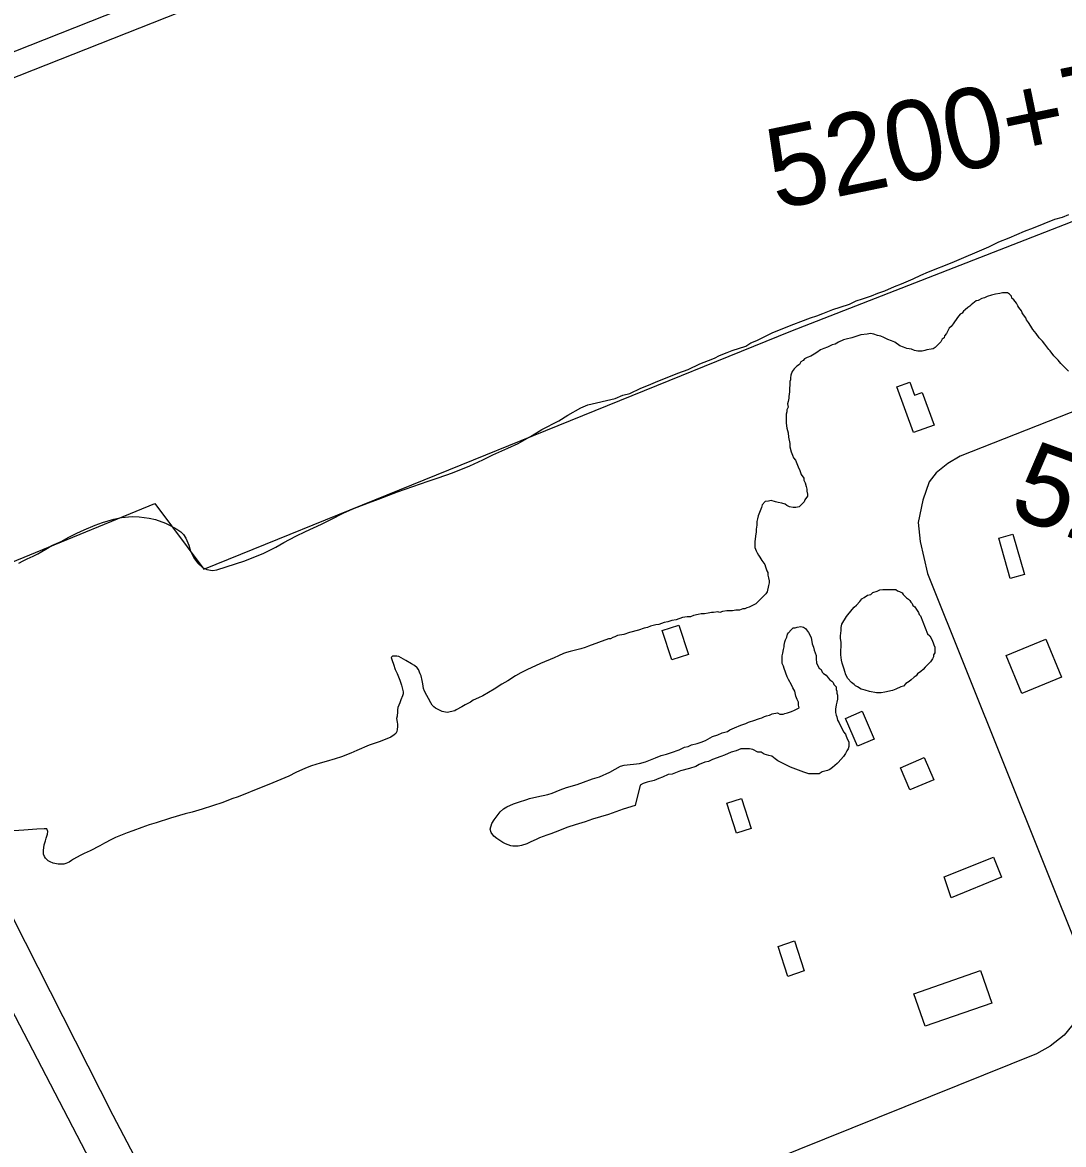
# Model space of a CAD drawing. Extents: x 3324125 to 3362000, y 600753 to 626151.
# Drawn here: x 3330131 to 3331428, y 615545 to 616943 of the extents above; entities that cross this region are included whole.
import ezdxf

# ---------------------------------------------------------------- set-up
doc = ezdxf.new("R2010")
doc.units = 0
for name, color, linetype in [('V-BLDG-OTLN', 7, 'Continuous'), ('V-ROAD-CNTR', 7, 'Continuous'), ('V-SITE-VEGE', 7, 'Continuous'), ('V-SURV-IDEN', 7, 'Continuous'), ('V-TOPO-SHOR', 7, 'Continuous')]:
    doc.layers.add(name, color=color, linetype=linetype)

msp = doc.modelspace()

# ---------------------------------------------------------------- linework, layer by layer
at = {"layer": 'V-BLDG-OTLN'}
for points in [[(3331251.8, 616482.1), (3331266.7, 616441.5), (3331240.9, 616432), (3331220, 616488.9), (3331236.3, 616494.9), (3331242.3, 616478.6)], [(3331364.8, 616305.5), (3331379.2, 616255.3), (3331361.6, 616250.2), (3331347.2, 616300.5)], [(3330948.7, 616192.1), (3330960.5, 616155.6), (3330939.7, 616149), (3330927.9, 616185.4)], [(3331356.5, 616154.2), (3331405.9, 616174.5), (3331425.4, 616127.2), (3331376, 616106.8)], [(3331177, 616084.9), (3331192, 616050.3), (3331171.3, 616041.3), (3331156.3, 616076)], [(3331254.4, 616027.3), (3331266.2, 615999.6), (3331236.4, 615986.9), (3331224.6, 616014.6)], [(3331026.5, 615976.3), (3331038.6, 615938.9), (3331020.4, 615933), (3331008.2, 615970.3)], [(3331279.2, 615878.5), (3331340.6, 615902.9), (3331350.7, 615878), (3331287.8, 615852.6)], [(3331092.8, 615798.7), (3331104.9, 615761.3), (3331084.5, 615754.6), (3331072.3, 615792)], [(3331241.5, 615732.8), (3331324.5, 615761.7), (3331338.6, 615721.3), (3331255.6, 615692.4)]]:
    msp.add_lwpolyline(points, close=True, dxfattribs=at)
at = {"layer": 'V-ROAD-CNTR'}
for points in [[(3328654.4, 618531.3), (3329365.9, 617157.1), (3329945, 616043.4), (3330528.3, 614922), (3330989.5, 614026.8), (3331101.4, 613813.5), (3331202.1, 613623.7), (3331288.2, 613468), (3331370, 613325.9), (3331489, 613122.4), (3331566.5, 612992.9), (3331683.8, 612804.9), (3331896.1, 612486.7), (3332030.8, 612296.1), (3332261.4, 611985.3), (3332414.1, 611792.3), (3332593.4, 611567.9), (3332751.8, 611383.2), (3332947.9, 611162.2), (3333176.2, 610911.4), (3333408.7, 610672.1), (3333754.4, 610344.1), (3333997.3, 610124.4), (3334416.3, 609777.9)], [(3329622.7, 616703.3), (3329633, 616708.7), (3329640.7, 616710), (3329667.1, 616715.1), (3329709.7, 616718.1), (3329737.4, 616721.6), (3329760, 616732.4), (3330393.7, 616983), (3332211.8, 617656.7), (3332230.2, 617667.1), (3332245.9, 617675.2), (3332252, 617676.6), (3332287.8, 617678.2)], [(3329608.8, 616729.9), (3329623.3, 616737.5), (3329635.4, 616739.5), (3329663.2, 616744.9), (3329706.7, 616747.9), (3329728.8, 616750.8), (3329748, 616759.9), (3330382.9, 617011), (3330469.2, 617043)], [(3332062.8, 616703.3), (3331299.1, 616402.5), (3331283.7, 616393.5), (3331269.2, 616382.1), (3331260.5, 616370.6), (3331252.7, 616347.9), (3331246.8, 616320), (3331249.3, 616296.2), (3331258.3, 616256.3), (3331450.3, 615777.5), (3331453.2, 615748.7), (3331451.9, 615720), (3331443.3, 615699.2), (3331428.9, 615681.4), (3331411.3, 615667.7), (3331394.3, 615658.1), (3330239.3, 615193.5), (3328629.8, 614542.4), (3328220.6, 614377)]]:
    msp.add_lwpolyline(points, dxfattribs=at)
at = {"layer": 'V-SITE-VEGE'}
for points in [[(3330960.1, 616510.7), (3330974.5, 616517.8), (3330985.7, 616521.7), (3330992.9, 616524.8), (3330999.3, 616528), (3331008.8, 616531.9), (3331015.2, 616534.2), (3331032, 616539.7), (3331038.4, 616543.7), (3331045.6, 616546.8), (3331064.8, 616556.2), (3331075.9, 616560.9), (3331091.9, 616567.2), (3331100.7, 616570.3), (3331112.7, 616575), (3331120.6, 616577.4), (3331127.8, 616580.5), (3331140.6, 616585.2), (3331149.4, 616588.3), (3331161.4, 616592.2), (3331169.4, 616596.2), (3331177.3, 616598.5), (3331188.5, 616602.4), (3331196.5, 616605.6), (3331205.3, 616608.7), (3331217.3, 616614.2), (3331226, 616617.3), (3331240.4, 616623.6), (3331250, 616628.3), (3331259.6, 616632.2), (3331289.1, 616644), (3331334.7, 616663.6), (3331347.5, 616669.9), (3331360.2, 616674.6), (3331379.4, 616683.2), (3331390.6, 616687.1), (3331416.9, 616698.1), (3331426.5, 616700.5), (3331434.5, 616703.6)], [(3331434, 616508.4), (3331424.5, 616518.1), (3331421.4, 616522.1), (3331415.8, 616527.7), (3331411.1, 616534.1), (3331409.5, 616535.7), (3331404.8, 616542.1), (3331401.6, 616546.1), (3331397.7, 616550.1), (3331393.7, 616555.7), (3331389.8, 616560.5), (3331387.4, 616564.5), (3331384.2, 616569.3), (3331381.9, 616572.5), (3331381.1, 616574.9), (3331377.9, 616578.9), (3331376.4, 616581.3), (3331375.6, 616583.7), (3331372.4, 616587.7), (3331370.8, 616590.1), (3331369.3, 616593.3), (3331366.1, 616597.3), (3331363.7, 616599.7), (3331363, 616602.1), (3331360.6, 616604.5), (3331358.2, 616606.1), (3331351.8, 616606.2), (3331348.6, 616605.4), (3331343.1, 616604.6), (3331338.3, 616603.1), (3331332.7, 616601.5), (3331329.5, 616599.9), (3331326.3, 616599.2), (3331321.5, 616596.8), (3331319.1, 616596), (3331312.7, 616591.3), (3331311.1, 616589.7), (3331308.7, 616588.1), (3331305.5, 616584.9), (3331303.1, 616583.4), (3331301.5, 616581), (3331299.1, 616579.4), (3331295.9, 616575.4), (3331294.3, 616573.1), (3331291.9, 616569.9), (3331290.2, 616567.5), (3331287.8, 616564.3), (3331285.4, 616562), (3331282.2, 616555.6), (3331279.8, 616552.5), (3331279, 616550.1), (3331276.6, 616548.5), (3331275, 616545.3), (3331267.8, 616538.2), (3331265.4, 616536.6), (3331263, 616535.8), (3331257.4, 616535.1), (3331255, 616534.3), (3331251.8, 616533.5), (3331246.2, 616533.6), (3331242.2, 616534.4), (3331238.3, 616536), (3331232.7, 616536.8)], [(3331232.7, 616536.8), (3331228.7, 616538.4), (3331224, 616540.1), (3331217.6, 616544.9), (3331213.6, 616546.5), (3331208.9, 616548.1), (3331204.1, 616550.6), (3331200.1, 616552.2), (3331196.2, 616553), (3331191.4, 616554.6), (3331187.4, 616555.4), (3331183.4, 616554.7), (3331175.5, 616553.9), (3331169.1, 616551.6), (3331164.3, 616550), (3331157.1, 616548.5), (3331153.9, 616547.7), (3331147.5, 616544.5), (3331143.5, 616542.2), (3331139.5, 616541.4), (3331133.9, 616538.3), (3331129.1, 616536.7), (3331125.2, 616535.1), (3331120.4, 616532), (3331117.2, 616529.6), (3331113.2, 616527.2), (3331108.4, 616525.7), (3331105.2, 616524.1), (3331103.6, 616521.7), (3331100.4, 616520.2), (3331098.8, 616517), (3331095.6, 616514.6), (3331092.3, 616511.4), (3331089.9, 616508.3), (3331088.3, 616503.5), (3331087.5, 616500.3), (3331087.5, 616497.9), (3331086.7, 616495.6), (3331086.6, 616482.8), (3331085.8, 616477.2), (3331085.7, 616474.8), (3331084.9, 616470.9), (3331084.1, 616467.7), (3331084.9, 616463.7), (3331083.3, 616460.5), (3331083.2, 616458.1), (3331082.4, 616455), (3331082.4, 616443.8), (3331083.1, 616437.4), (3331084.7, 616431.8), (3331085.4, 616426.3), (3331087, 616418.3), (3331086.9, 616414.3), (3331088.5, 616407.9), (3331090.1, 616403.9), (3331091.6, 616400.7), (3331094, 616397.5), (3331097.1, 616389.5), (3331099.5, 616384.8), (3331101.1, 616380), (3331104.2, 616375.2), (3331104.2, 616372.8), (3331105.8, 616369.6), (3331107.3, 616364.8), (3331108.1, 616361.6), (3331108.1, 616359.2), (3331108.9, 616355.2), (3331108.8, 616352.8), (3331105.6, 616348.1), (3331104.8, 616345.7), (3331098.4, 616339.4), (3331094.4, 616338.6), (3331091.2, 616338.6), (3331086.5, 616339.4), (3331083.3, 616341.1), (3331080.9, 616342.7), (3331076.9, 616344.3), (3331072.2, 616345.1), (3331069, 616345.9), (3331063.4, 616347.6), (3331060.2, 616346.8), (3331056.2, 616346), (3331052.2, 616342), (3331051.4, 616338.9), (3331047.4, 616328.5), (3331046.5, 616324.6), (3331045.7, 616321.4), (3331045.7, 616316.6), (3331044.9, 616311.8), (3331044.8, 616308.6), (3331044, 616303.1), (3331043.2, 616295.9), (3331043.1, 616288.7), (3331044.7, 616284.7), (3331046.3, 616282.3), (3331047.8, 616279.2), (3331049.4, 616276.7), (3331051.8, 616272.8), (3331055.7, 616267.9), (3331056.5, 616264.8), (3331058.1, 616260)], [(3330126.2, 616269.4), (3330131.4, 616272.2), (3330136.3, 616274.7), (3330143.9, 616278.2), (3330149.6, 616281.2), (3330159.5, 616287), (3330167.3, 616291.2), (3330178.6, 616296.4), (3330188.5, 616301.6), (3330198.5, 616306.6), (3330207.4, 616310.8), (3330221.3, 616316.7), (3330230.4, 616320), (3330244.4, 616324.3), (3330253.8, 616326.2), (3330267.4, 616327.5), (3330275.9, 616327), (3330288.3, 616325.6), (3330296.5, 616323.6), (3330308.7, 616319.4), (3330314.7, 616316.1), (3330322.8, 616311.8), (3330327.8, 616308.6), (3330331.1, 616305.1), (3330334, 616300.6), (3330337.8, 616291.9), (3330339.9, 616284.5), (3330344.9, 616274.7), (3330348.9, 616269.3), (3330355.1, 616263.8), (3330360.2, 616261.4), (3330367.3, 616260.4), (3330372.8, 616261.2), (3330407.8, 616272.4), (3330431.2, 616281.9), (3330446.4, 616289.4), (3330456.1, 616295), (3330471.1, 616302.9), (3330483.4, 616308.8), (3330503.1, 616318), (3330515, 616323.9), (3330530.4, 616331.8), (3330542.4, 616337), (3330561.7, 616344.4), (3330574.4, 616349), (3330598.1, 616358.4), (3330636.1, 616371.5), (3330648.7, 616375.5), (3330666.6, 616381.8), (3330688.1, 616390.6), (3330704.4, 616398.3), (3330716.7, 616404.2), (3330735.4, 616412.6), (3330748.3, 616418.6), (3330765.6, 616428.4), (3330777.9, 616435.7), (3330798.9, 616446.8), (3330810.4, 616453.9), (3330826.4, 616463.1), (3330835, 616466.6), (3330869.1, 616474.7), (3330878.7, 616478.6), (3330887.4, 616480.9), (3330901, 616487.2), (3330910.6, 616491.1), (3330919.4, 616495), (3330947.3, 616506), (3330960.1, 616510.7)], [(3331058.1, 616260), (3331059.6, 616257.6), (3331059.6, 616254.4), (3331060.4, 616251.2), (3331061.2, 616247.2), (3331061.2, 616244.8), (3331060.3, 616241.6), (3331058.7, 616233.7), (3331057.1, 616231.3), (3331044.3, 616218.6), (3331036.3, 616214.7), (3331033.1, 616213.9), (3331030.7, 616212.4), (3331028.3, 616212.4), (3331024.3, 616210.8), (3331019.5, 616210.8), (3331015.5, 616210.1), (3331008.4, 616210.1), (3331002.8, 616209.3), (3330999.6, 616207.8), (3330997.2, 616208.6), (3330991.6, 616207.8), (3330989.2, 616207.8), (3330985.2, 616207.1), (3330980.5, 616206.3), (3330976.5, 616206.3), (3330972.5, 616205.6), (3330966.9, 616204), (3330962.9, 616202.4), (3330958.9, 616202.5), (3330953.3, 616201.7), (3330945.4, 616198.6), (3330939.8, 616197.8), (3330935, 616196.2), (3330930.2, 616195.5), (3330923.8, 616193.1), (3330919.8, 616192.4), (3330913.4, 616190.8), (3330909.5, 616189.2), (3330905.5, 616188.5), (3330898.3, 616186.1), (3330887.1, 616183), (3330879.9, 616180.7), (3330872, 616179.1), (3330868.8, 616177.6), (3330866.4, 616176.8), (3330863.2, 616175.2), (3330860.8, 616175.2), (3330836, 616165.9), (3330834, 616165.3), (3330831.7, 616164.2), (3330826.4, 616162.5), (3330816.5, 616160), (3330813.2, 616159.5), (3330808.5, 616158.1), (3330804.6, 616156.8), (3330798.6, 616154.1), (3330793.3, 616151.6), (3330776, 616144.5), (3330758.9, 616136.5), (3330751.7, 616132.9), (3330745, 616129.2), (3330735.3, 616122.9), (3330728.1, 616118.8), (3330718.3, 616112.3), (3330704.1, 616104), (3330699, 616101.7), (3330692.4, 616098.5), (3330688.7, 616096.2), (3330682.4, 616092.7), (3330678.2, 616090.2), (3330671.1, 616086.6), (3330669.4, 616085.4), (3330659.9, 616083.3), (3330653.6, 616084.7), (3330650.2, 616086.3), (3330645.1, 616088.9), (3330643.2, 616090.4), (3330641.3, 616092.4), (3330639.3, 616095.5), (3330636.7, 616100.8), (3330634.4, 616104.5), (3330631.5, 616109.7), (3330630.5, 616113.1), (3330629.4, 616118.9), (3330628.8, 616123), (3330627.5, 616129), (3330626.2, 616131.7), (3330624.1, 616136.8), (3330622.3, 616138.9), (3330619.1, 616141.7), (3330615.4, 616144), (3330608.2, 616148.2), (3330599.5, 616152.9), (3330597, 616153.5), (3330591.9, 616153.7), (3330590, 616151.8), (3330591.1, 616148.1), (3330593, 616143.6), (3330595.1, 616137), (3330597.4, 616131.9)], [(3330919.6, 616026.7), (3330926.7, 616029.8), (3330933.1, 616031.4), (3330939.5, 616033.7), (3330949.1, 616036.8), (3330955.5, 616040), (3330960.3, 616040.8), (3330964.3, 616043.1), (3330971.4, 616044.7), (3330976.2, 616046.2), (3330981.8, 616048.6), (3330990.6, 616053.3), (3330997, 616055.7), (3331002.6, 616058), (3331009, 616059.6), (3331012.2, 616061.9), (3331017.8, 616064.3), (3331025.8, 616067.4), (3331032.1, 616069.8), (3331035.3, 616071.3), (3331037.7, 616072.1), (3331040.9, 616072.9), (3331048.9, 616076), (3331052.1, 616076.8), (3331055.3, 616078.4), (3331057.7, 616079.2), (3331061.7, 616079.9), (3331064.9, 616081.5), (3331071.3, 616083.1), (3331074.4, 616081.4), (3331078.4, 616081.4), (3331080.8, 616082.2), (3331084, 616083), (3331088.8, 616084.5), (3331092.8, 616086.1), (3331096, 616087.7), (3331098.4, 616089.2), (3331097.6, 616092.4), (3331097.6, 616096.4), (3331096.1, 616099.6), (3331094.5, 616103.6), (3331092.9, 616110), (3331090.6, 616114), (3331089, 616118), (3331085.1, 616124.4), (3331083.5, 616127.6), (3331079.6, 616138), (3331078.8, 616141.2), (3331077.2, 616144.3), (3331077.3, 616153.9), (3331078.1, 616157.1), (3331078.9, 616161.9), (3331079.8, 616165), (3331079.8, 616167.4), (3331080.6, 616171.4), (3331081.4, 616173.8), (3331083, 616177), (3331083.8, 616180.9), (3331085.4, 616182.5), (3331088.7, 616186.5), (3331091.1, 616188.9), (3331093.4, 616188.8), (3331095.8, 616189.6), (3331100.6, 616190.4), (3331103.8, 616189.6), (3331106.2, 616188), (3331107.8, 616186.4), (3331110.1, 616183.2), (3331113.3, 616176.8), (3331114.8, 616168.8), (3331116.4, 616164.8), (3331117.2, 616160.8), (3331119.5, 616154.4), (3331119.5, 616150.4), (3331120.2, 616144.9), (3331123.4, 616138.5), (3331125.8, 616136.9), (3331127.3, 616133.7), (3331128.9, 616132.1), (3331132.1, 616129.7), (3331134.5, 616126.5), (3331136.8, 616124), (3331139.2, 616122.4), (3331140.8, 616120.8), (3331141.6, 616118.4), (3331144.7, 616115.2), (3331144.7, 616112), (3331145.5, 616109.7), (3331145.5, 616107.3), (3331146.3, 616104.9), (3331146.2, 616100.1), (3331145.4, 616096.1), (3331144.6, 616092.9), (3331143.8, 616087.4), (3331143.7, 616083.4), (3331144.5, 616080.2), (3331145.3, 616077.8), (3331146.1, 616073.8)], [(3330597.4, 616131.9), (3330600.9, 616123.7), (3330602.8, 616117.5), (3330604.9, 616109.1), (3330605.2, 616106.4), (3330604.1, 616104.3), (3330602.1, 616099.3), (3330600.7, 616095.2), (3330598.5, 616089.4), (3330597.9, 616086.7), (3330597.9, 616084.1), (3330597.5, 616078.7), (3330596.7, 616075.8), (3330597.4, 616071.3), (3330598, 616068.6), (3330598, 616065.9), (3330597.4, 616062), (3330597.2, 616059.5), (3330595.8, 616057), (3330593.8, 616055.4), (3330589.7, 616052.7), (3330576.3, 616047.2), (3330562.7, 616042.6), (3330547.1, 616035.9), (3330539.9, 616032.6), (3330528, 616028.3), (3330520.2, 616025.6), (3330508.9, 616022.2), (3330501.5, 616020.3), (3330490.7, 616016.8), (3330483.2, 616013.8), (3330471.4, 616008.4), (3330462.4, 616004), (3330437.5, 615993.7), (3330428.1, 615989.7), (3330399.5, 615978.4), (3330391.5, 615975.7), (3330380.4, 615971.3), (3330354.3, 615962.8), (3330341.9, 615959.2), (3330333.3, 615956.9), (3330315.2, 615951.7), (3330297.1, 615945.8), (3330288.6, 615943.2), (3330279.4, 615940.1), (3330267.9, 615936.1), (3330260.9, 615933.5), (3330246.7, 615927.5), (3330241.5, 615925), (3330232.7, 615920.4), (3330227, 615917.2), (3330215, 615910.8), (3330207.4, 615907.6), (3330202.3, 615905.3), (3330194.3, 615900.7), (3330191.6, 615898.9), (3330188.8, 615897), (3330184.7, 615895.1), (3330182.2, 615894.5), (3330177.7, 615894.2), (3330175.2, 615894.4), (3330168.8, 615895.8), (3330165, 615897.2), (3330162.4, 615898.5), (3330159.2, 615901.9), (3330158, 615903.8), (3330156.7, 615906.9), (3330156.7, 615911.6), (3330157.7, 615918.4), (3330159.3, 615923.4), (3330160.1, 615926.7), (3330161.9, 615931.8), (3330162.1, 615935.1), (3330161.1, 615938.4), (3330157.8, 615938.4), (3330148.3, 615937.9), (3330142.9, 615937.5), (3330132.4, 615936.6), (3330119.6, 615935.9)], [(3331146.1, 616073.8), (3331148.4, 616070.6), (3331153.9, 616059.4), (3331156.3, 616056.2), (3331157.1, 616053.8), (3331158.7, 616049.8), (3331160.2, 616046.6), (3331160.2, 616041.1), (3331159.4, 616037.9), (3331157.8, 616035.5), (3331156.2, 616032.3), (3331153.7, 616028.4), (3331147.3, 616021.2), (3331145.7, 616019.6), (3331140.1, 616014.9), (3331136.9, 616012.5), (3331133.7, 616011), (3331127.3, 616009.4), (3331123.3, 616007), (3331110.6, 616007.1), (3331104.2, 616008.8), (3331087.5, 616015.2), (3331071.7, 616023.3), (3331068.5, 616025.7), (3331064.5, 616028.9), (3331060.6, 616029.8), (3331055, 616031.4), (3331051, 616033.8), (3331047, 616033.8), (3331040.7, 616037.1), (3331036.7, 616037.9), (3331025.6, 616037.9), (3331020, 616035.6), (3331013.6, 616034), (3331005.6, 616030.1), (3331000.8, 616028.5), (3330990.4, 616024.6), (3330985.6, 616022.3), (3330980.9, 616021.5), (3330973.7, 616018.4), (3330969.7, 616016), (3330961.7, 616013.7), (3330950.5, 616010.6), (3330940.1, 616006.6), (3330935.4, 616005.9), (3330928.2, 616002.7), (3330923.4, 616001.2), (3330917.8, 615998.8), (3330909, 615996.5), (3330904.2, 615994.9), (3330900.2, 615992.6), (3330894.1, 615967.4), (3330879.3, 615962.7), (3330860.8, 615956.2), (3330841, 615950.3), (3330831.6, 615947.2), (3330819.2, 615943.4), (3330810.2, 615940.6), (3330804.6, 615938.5), (3330799.7, 615936.2), (3330789, 615932), (3330783.9, 615930.3), (3330775, 615927), (3330770.9, 615925.1), (3330763.9, 615922.2), (3330759.2, 615919.9), (3330752.4, 615917.7), (3330748.3, 615916.7), (3330741.7, 615916.8), (3330739.2, 615917.4), (3330732.6, 615919.7), (3330729.3, 615921.3), (3330721.6, 615926.4), (3330718.1, 615929.3), (3330714.8, 615934), (3330713.3, 615937.9), (3330715.5, 615945.1), (3330718.2, 615949.7), (3330723.5, 615956.3), (3330725.7, 615959.6), (3330730.2, 615963.2), (3330734.3, 615965.6), (3330742.4, 615969.4), (3330748.7, 615971.7), (3330759, 615974.9), (3330762.3, 615976.1), (3330771.4, 615978.1), (3330785.4, 615981.1), (3330790.7, 615982.7), (3330800.8, 615986.9), (3330808.6, 615989.7), (3330821.8, 615993.7), (3330829.8, 615996.4), (3330841.1, 616000.6), (3330849.7, 616003.3), (3330862.5, 616008.8), (3330876, 616016.3), (3330880.6, 616017.8), (3330899.6, 616019.6), (3330906.8, 616022), (3330919.6, 616026.7)]]:
    msp.add_lwpolyline(points, dxfattribs=at)
msp.add_lwpolyline([(3331258.3, 616181.4), (3331261.5, 616179), (3331263.8, 616174.2), (3331265.4, 616170.2), (3331266.2, 616167.8), (3331267.7, 616164.6), (3331267.7, 616157.5), (3331266.1, 616155.1), (3331266.1, 616152.7), (3331264.5, 616150.3), (3331262, 616146.3), (3331255.6, 616140), (3331253.2, 616136.8), (3331250, 616134.5), (3331246, 616131.3), (3331244.4, 616128.9), (3331242, 616127.4), (3331238, 616124.2), (3331235.6, 616121.8), (3331231.6, 616119.5), (3331228.4, 616116.3), (3331225.2, 616115.5), (3331218.8, 616112.4), (3331214.8, 616110.8), (3331205.2, 616108.5), (3331200.5, 616107.7), (3331194.9, 616107.7), (3331186.1, 616109.4), (3331180.6, 616111), (3331175.8, 616112.6), (3331171, 616115.1), (3331168.6, 616116.7), (3331167.1, 616118.3), (3331163.9, 616120.7), (3331159.1, 616125.5), (3331156.8, 616130.3), (3331155.2, 616134.3), (3331154.4, 616137.5), (3331152.1, 616144.7), (3331151.3, 616148.6), (3331150.6, 616155), (3331150.7, 616171), (3331149.9, 616175.7), (3331149.9, 616178.9), (3331150.8, 616185.3), (3331150.8, 616189.3), (3331151.6, 616193.2), (3331157.3, 616202.8), (3331164.5, 616211.5), (3331166.9, 616214.7), (3331170.1, 616217), (3331174.1, 616221.8), (3331176.5, 616225), (3331179.7, 616226.5), (3331183.7, 616229.7), (3331187.7, 616230.5), (3331190.1, 616232.8), (3331195.7, 616234.4), (3331198.9, 616236), (3331202.9, 616236.7), (3331218.8, 616236.6), (3331221.2, 616235), (3331223.6, 616234.2), (3331226.8, 616232.6), (3331228.3, 616230.2), (3331230.7, 616227.8), (3331232.3, 616226.2), (3331234.7, 616224.6), (3331236.2, 616223), (3331237.8, 616220.6), (3331239.4, 616219), (3331240.2, 616216.6), (3331242.6, 616215), (3331244.9, 616211.8), (3331247.3, 616207.8), (3331248.1, 616205.4), (3331249.7, 616203.8)], close=True, dxfattribs=at)
at = {"layer": 'V-TOPO-SHOR'}
for points in [[(3329983.4, 616216), (3330295.4, 616343.8), (3330356.7, 616262), (3331088, 616558.6), (3331941.9, 616891), (3331967.5, 616880.7), (3332023.7, 616901.2)], [(3330243.8, 615581.2), (3330103, 615858.3), (3329971.7, 616106.2), (3329848, 616347.1), (3329724.4, 616598.5), (3329696.3, 616650.6)], [(3330407.7, 615281.7), (3330361.9, 615359.3), (3330318.2, 615438.9), (3330243.8, 615581.2)]]:
    msp.add_lwpolyline(points, dxfattribs=at)

# ---------------------------------------------------------------- texts
at = {"layer": 'V-SURV-IDEN'}
for s, rotation, p in [('5200+74.2', 11.6907, (3331069.8, 616709.7)), ('5208+79.0', 339.8878, (3331357, 616330.2))]:
    msp.add_text(s, height=100, rotation=rotation, dxfattribs=at).set_placement(p)

doc.saveas('drawing.dxf')
